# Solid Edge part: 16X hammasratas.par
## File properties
Author: Türk
Template: Iso Part.par
Last saved by: Türk
Revision: 4
Application: Solid Edge
Accuracy: 0,990
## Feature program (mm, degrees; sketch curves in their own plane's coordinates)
pattern "PatternOccurrence_5"  XOffset = 22.5 deg
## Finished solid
Body 1: solid body, 68 faces, 194 edges, 128 vertices.
  Faces by surface: plane 51, cylinder 17
  Edges by curve: line 144, circle 34, intersection 16
Bounding box of the edges (mm): 26.000 x 80.000 x 26.000, from (-13, 0, -13) to (13, 80, 13).
Cylindrical faces by radius (mm): R6 x1, R11 x16
Planar faces by outward normal: +x 1, +y 2, +z 1, -x 1, -y 1, -z 1, oblique 44
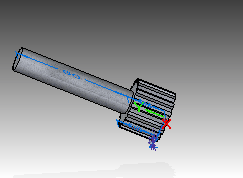
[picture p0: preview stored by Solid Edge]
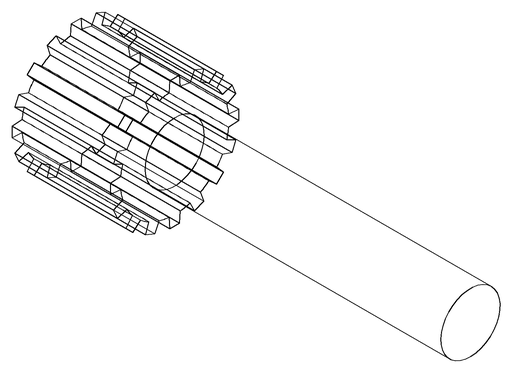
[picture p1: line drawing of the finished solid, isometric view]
